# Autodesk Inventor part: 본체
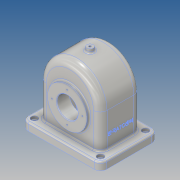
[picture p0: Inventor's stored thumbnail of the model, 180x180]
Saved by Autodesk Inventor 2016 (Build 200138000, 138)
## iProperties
Created: 2016-10
Part Number: 본체
Material: 알루미늄 6061
Document SubType Name: Modeling
Designer: Administrator
Density: 2.7 g/cm^3
Appearance: 알루미늄 - 평지
Mass: 1160.82 g
Surface Area: 1199.98 cm^2
Volume: 429.934 cm^3
Author: Administrator
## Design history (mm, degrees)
sketch "스케치1"
  geometry: L1 (-58, 0)-(58, 0); L2 (58, 0)-(58, -80); L3 (58, -80)-(-58, -80); L4 (-58, -80)-(-58, 0); L5 (-81.2, 0)-(81.2, 0) reference; L6 (0, -107.6)-(0, 85.6) reference; A1 r 58 centre (0, 0) between (58, 0) and (-58, 0); 1 further point
  constraints: 8 end point, 2 parallel, 2 point on circle, 2 point on line, 1 centre point, 1 coincident, 1 collinear, 1 horizontal, 1 perpendicular, 1 other
  dimensions: "d1" = 80 distance of L3.end L1.start; "d2" = 58 radius of A1
extrude "돌출1" new body sketch "스케치1" stored distance "d3" = 77; taper "d4" = 0 deg
fillet "모깎기1" dims "d5" = 13
sketch "스케치3"
  geometry: L1 (0, -25.5)-(0, 25.5) reference; L2 (0, 25.5)-(0, -25.5) reference; L3 (0, -25.5)-(0, -25.5) reference; L4 (0, 25.5)-(0, 25.5) reference; 1 further point
  node "투영된 루프1"
sketch "스케치4"
  geometry: L1 (-30, 16.5)-(120, 16.5); L2 (120, 16.5)-(120, -93.5); L3 (120, -93.5)-(-30, -93.5); L4 (-30, -93.5)-(-30, 16.5); L5 (-30, 16.5)-(120, -93.5); L6 (120, 16.5)-(-30, -93.5); 1 further point
  constraints: 12 end point, 2 midpoint, 2 parallel, 1 horizontal, 1 perpendicular
  dimensions: "d16" = 110 distance of L1.end L2.end; "d17" = 150 distance of L2.end L3.end
extrude "돌출2" join sketch "스케치4" distance "d18" = 15; taper "d19" = 0 deg
fillet "모깎기2" dims "d20" = 12
sketch "스케치6"
  geometry: A1 r 12 centre (-18, -4.5) between (-30, -4.5) and (-18, -16.5) reference; A2 r 12 centre (108, -4.5) between (108, -16.5) and (120, -4.5) reference; A3 r 12 centre (108, 81.5) between (120, 81.5) and (108, 93.5) reference; A4 r 12 centre (-18, 81.5) between (-18, 93.5) and (-30, 81.5) reference; 1 further point
hole "구멍1" sketch "스케치6" at (-18, 81.5), (-18, -4.5), (108, -4.5), (108, 81.5) diameter "d21" = 5; stored, may be unused: countersink angle "d25" = 90 deg, drill point angle "d27" = 118 deg; dims "d22" = 6, "d23" = 12, "d24" = 5, "d26" = 8
fillet "모깎기3" dims "d28" = 3
node "작업 평면1"
sketch "스케치7"
  geometry: C1 r 6 at (0, 0); 1 further point
  constraints: 1 centre point, 1 coincident
  dimensions: "d30" = 12 diameter of C1
extrude "돌출3" join sketch "스케치7" stored distance "d31" = 15; taper "d32" = 0 deg
sketch "스케치9"
  geometry: L1 (-58, -65)-(-58, 0) reference; L2 (58, 0)-(58, -65) reference; L3 (63, -80)-(-63, -80) reference; L4 (-52, -80)-(-52, 0); L5 (52, 0)-(52, -80); L6 (-105, 0)-(105, 0) reference; L7 (0, -108.8)-(0, 92.8) reference; A1 r 58 centre (0, 0) between (58, 0) and (-58, 0) reference; A2 r 52 centre (0, 0) between (52, 0) and (-52, 0); 1 further point
  constraints: 4 end point, 2 point on circle, 2 point on line, 1 centre point
  dimensions: "d45" = 6 radial gap between concentric circles of A1 A2; "d46" = 80 distance of L5.start L5.end; "d47" = 80 distance of L4.start L4.end; "d48" = 104 distance of L5.end L4.start
extrude "돌출4" cut sketch "스케치9" stored distance "d49" = 67; taper "d50" = 0 deg
sketch "스케치10"
  geometry: L1 (-65, 38.5)-(0, 38.5) reference; L2 (-15, 38.5)-(-15, -38.5); L3 (0, -38.5)-(-65, -38.5) reference; L4 (-80, -55)-(-80, -43) reference; L5 (-15, 38.5)-(-15, 43.5); L6 (0, 38.5)-(45, 38.5) reference; L7 (-15, 43.5)-(22.5, 43.5); L8 (22.5, 43.5)-(22.5, 33.5); L9 (52, 33.5)-(0, 33.5) reference; L10 (13, 19.5)-(-15, 19.5); L11 (13, 19.5)-(24.747, 33.5); L12 (24.747, 33.5)-(22.5, 33.5); L13 (58, 25.5)-(0, 25.5) reference; 1 further point
  constraints: 14 end point, 5 point on line, 2 perpendicular, 2 vertical, 1 horizontal, 1 parallel
  dimensions: "d51" = 65 distance between parallel lines of L4 L2; "d52" = 5 distance of L2.start L5.end; "d54" = 37.5 distance of L5.end L7.end; "d114" = 28 distance of L10.end L10.start; "d115" = 50 deg angle of L10 L11; "d116" = 24 distance between parallel lines of L10 L7
revolve "회전1" sketch "스케치10" stored, may be unused: angle "d57" = 90 deg
hole "구멍2" diameter "d60" = 40; stored, may be unused: countersink angle "d64" = 90 deg, drill point angle "d66" = 118 deg; dims "d58" = 10, "d59" = 10, "d61" = 6, "d62" = 12, "d63" = 5, "d65" = 8
sketch "스케치11"
  geometry: C1 r 20 at (0, -15) reference; C2 r 31 at (0, -15)
  constraints: 1 centre point, 1 coincident
  dimensions: "d67" = 62 diameter of C2
extrude "돌출5" join sketch "스케치11" distance "d68" = 10; taper "d69" = 0 deg
sketch "스케치12" dims "d70" = 52
  geometry: L1 (105, 15)-(-105, 15) reference; L2 (0, -93.8)-(0, 107.8) reference; C1 r 31 at (0, 0) reference; 3 further points
  constraints: 1 coincident, 1 point on line, 1 vertical alignment, 2 other
hole "구멍3" sketch "스케치12" at (0, 26) diameter "d71" = 2.459; stored, may be unused: countersink angle "d75" = 90 deg, drill point angle "d77" = 118 deg; dims "d72" = 6, "d73" = 12, "d74" = 5, "d76" = 8
sketch "스케치13" dims "d81" = 58
  geometry: L1 (-105, 15)-(105, 15) reference; L2 (0, -93.8)-(0, 107.8) reference; C1 r 37.5 at (0, 0) reference; 3 further points
  constraints: 1 coincident, 1 point on line, 1 vertical alignment, 2 other
hole "구멍4" sketch "스케치13" at (0, 29) diameter "d82" = 2.459; stored, may be unused: countersink angle "d86" = 90 deg, drill point angle "d88" = 118 deg; dims "d83" = 6, "d84" = 12, "d85" = 5, "d87" = 8
hole "구멍5" diameter "d94" = 4.134; stored, may be unused: countersink angle "d98" = 90 deg, drill point angle "d100" = 118 deg; dims "d92" = 10, "d93" = 10, "d95" = 10, "d96" = 12, "d97" = 5, "d99" = 14.2
node "작업 평면2"
sketch "스케치14"
  geometry: L1 (-108.8, 0)-(92.8, 0) reference; L2 (0, -77)-(0, 77) reference; L3 (0, 38.5)-(-65, 38.5) reference; L4 (-80, 43)-(-80, -43) reference; 2 further points
  constraints: 1 other
  dimensions: "d102" = 38.5 distance from line of point (-40, 0) L3; "d103" = 40 distance from line of L4 point (-40, 0)
feature "엠보싱1" sketch "스케치14" dims "d1" = 80, "d2" = 58, "d104" = 0.5, "d105" = 0
fillet "모깎기5" dims "d106" = 3
chamfer "모따기1" distance "d107" = 1; stored, may be unused: second distance "d108" = 2, angle "d109" = 45 deg
fillet "모깎기6" dims "d110" = 8
feature "면 기울기1" dims angle "d111" = 10 deg
fillet "모깎기7" dims "d112" = 3
fillet "모깎기8" dims "d113" = 3
node "솔리드1"
pattern_circular "원형 패턴1" dims angle "d79" = 360 deg
pattern_circular "원형 패턴2" dims angle "d90" = 360 deg
other parameters: "d29" = 64
